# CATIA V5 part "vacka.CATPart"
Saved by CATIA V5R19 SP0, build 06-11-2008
Part number: vacka
Bounding box of the stored display mesh (mm): x -170.45 to 170.444, y -170.451 to 168.809, z 5.5 to 50
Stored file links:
  C:\Users\Jozef Drozd\Desktop\zostava\party\vacka.CATPart
  C:\Users\Jozef Drozd\Desktop\nizsia\parts\Disk  D.1.CATPart
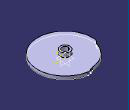
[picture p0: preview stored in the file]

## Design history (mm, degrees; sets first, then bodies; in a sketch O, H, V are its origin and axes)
Body1 (main body)
  Sketch1 on xy-plane, origin (0, 0, 0), H (1, 0, 0), V (0, 1, 0)
    arc A1 centre (0, 0) radius 156.9247 from (-12.9577, 156.3888) to (-148.5647, 50.5362) ccw
    arc A2 centre (-15.4349, 186.2864) radius 30 from (-12.9577, 156.3888) to (1.5564, 161.562) ccw
    line L1 (1.5564, 161.562) -> (4.4252, 163.5335)
    arc A3 centre (21.4165, 138.8091) radius 30 from (25.991, 168.4582) to (4.4252, 163.5335) ccw
    arc A4 centre (0, 0) radius 170.4515 from (-169.7518, 15.4281) to (25.991, 168.4582) ccw
    arc A5 centre (-139.875, 12.7127) radius 30 from (-169.7518, 15.4281) to (-160.4341, 34.5605) cw
    line L2 (-156.4073, 38.3497) -> (-160.4341, 34.5605)
    arc A6 centre (-176.9664, 60.1974) radius 30 from (-148.5647, 50.5362) to (-156.4073, 38.3497) cw
  Pad1: profile Sketch1, direction (0, 0, 1), length 25, opposite side length -5.5
  Sketch2 on end face of Pad1, origin (0, 0, 25), H (1, 0, 0), V (0, 1, 0)
    circle A1 centre (0, 0) radius 30
    point P1 (0, -30)
    coincidence: A1 P1, P1 V
  Pad2: profile Sketch2, direction (0, 0, 1), length 25
  Sketch3 on start face of Pad1, origin (0, 0, 5.5), H (1, 0, 0), V (0, -1, 0)
    circle A1 centre (0, 0) radius 20
    point P1 (0, -20)
    coincidence: A1 P1, P1 V
  Pocket1: profile Sketch3, direction (0, 0, 1), length 50
  Sketch4 on start face of Pad1, origin (0, 0, 5.5), H (1, 0, 0), V (0, -1, 0)
    arc A1 centre (0, 0) radius 156.9247 from (-148.5066, -50.7065) to (-12.7783, -156.4036) ccw
    arc A2 centre (-15.2212, -186.304) radius 30 from (-12.7783, -156.4036) to (0.9529, -161.0374) cw
    arc A3 centre (21.7838, -138.7519) radius 30 from (26.4368, -168.3889) to (5.6097, -164.0184) cw
    arc A4 centre (0, 0) radius 170.4515 from (26.4368, -168.3889) to (-169.7104, -15.8774) ccw
    arc A5 centre (-139.8408, -13.0829) radius 30 from (-169.7104, -15.8774) to (-159.6749, -35.591) ccw
    arc A6 centre (-176.8973, -60.4003) radius 30 from (-148.5066, -50.7065) to (-157.0632, -37.8923) ccw
    line L1 (-157.0632, -37.8923) -> (-159.6749, -35.591)
    line L2 (0.9529, -161.0374) -> (5.6097, -164.0184)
